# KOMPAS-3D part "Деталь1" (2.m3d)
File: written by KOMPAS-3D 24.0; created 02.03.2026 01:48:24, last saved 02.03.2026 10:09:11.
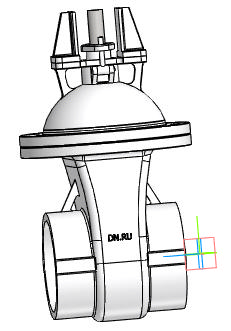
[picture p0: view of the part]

Document properties: Автор: R2D2; Полное имя файла: E:\Работа\Зайцев\GVWR2121M-2W-F-ОСТ Задвижка клиновая с видвижным штоком Ду50-300 Ру16\DN150\Исходные материалы\2.m3d

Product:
- Body: Твердое тело1  | qty 1
    Масса: 77.234324
- Part/product: Деталь1
    Масса: 77.234324
    additional columns: Типовые

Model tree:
1. Твердое тело1  (labels: Твердое тело1)
2. Эскиз:1
3. Элемент выдавливания:2
     Расстояние 1 = 500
